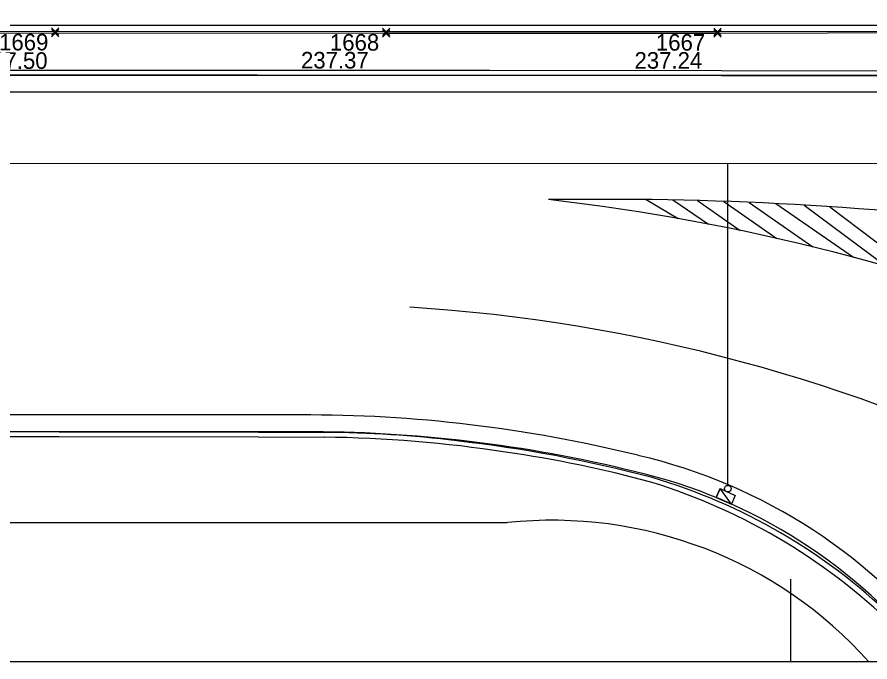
# Model space of a CAD drawing. Extents: x -264165 to -263733, y -1242319 to -1242245.
# Drawn here: x -263851.2 to -263825.46, y -1242319.19 to -1242299.73 of the extents above; entities that cross this region are included whole.
import ezdxf

# ---------------------------------------------------------------- set-up
doc = ezdxf.new("R2010")
doc.units = 0
for name, color, linetype in [('KFA_BOD_CISLO', 7, 'Continuous'), ('KFA_BOD_SYMBOL', 7, 'Continuous'), ('KFA_BOD_VYSKA', 7, 'Continuous'), ('KFA_SO_20-2_OBRUBNIKY_HORNA_HRANA', 7, 'Continuous'), ('PROJEKT_OBRUBNIKY_KOMUNIKACIE', 7, 'Continuous'), ('PROJEKT_TDZ_VODOROVNE', 7, 'Continuous'), ('RAM_NA_TLAC_1-250', 7, 'Continuous'), ('SITUACIA_DSP_2D', 7, 'Continuous'), ('SO_20-1_OBRUBNIKY_DOLNA_HRANA', 7, 'Continuous'), ('SO_20-1_OBRUBNIKY_HORNA_HRANA', 7, 'Continuous')]:
    doc.layers.add(name, color=color, linetype=linetype)

msp = doc.modelspace()

# ---------------------------------------------------------------- linework, layer by layer
at = {"layer": 'KFA_BOD_SYMBOL'}
for p, q in [((-263850.165, -1242300.271), (-263849.943, -1242300.049)), ((-263849.943, -1242300.271), (-263850.165, -1242300.049)), ((-263850.165, -1242300.32), (-263849.943, -1242300.1)), ((-263849.943, -1242300.32), (-263850.165, -1242300.1)), ((-263840.171, -1242300.282), (-263839.949, -1242300.061)), ((-263839.949, -1242300.282), (-263840.171, -1242300.061)), ((-263840.171, -1242300.332), (-263839.949, -1242300.11)), ((-263839.949, -1242300.332), (-263840.171, -1242300.11)), ((-263830.172, -1242300.282), (-263829.951, -1242300.061)), ((-263829.951, -1242300.282), (-263830.172, -1242300.061)), ((-263830.172, -1242300.332), (-263829.951, -1242300.11)), ((-263829.951, -1242300.332), (-263830.172, -1242300.11))]:
    msp.add_line(p, q, dxfattribs=at)
at = {"layer": 'KFA_SO_20-2_OBRUBNIKY_HORNA_HRANA'}
for points in [[(-263818.454, -1242300.127), (-263820.114, -1242300.153), (-263830.062, -1242300.171), (-263840.06, -1242300.171), (-263850.054, -1242300.16), (-263860.027, -1242300.174), (-263870.031, -1242300.18), (-263880.008, -1242300.187), (-263888.684, -1242300.195), (-263899.013, -1242300.19), (-263908.987, -1242300.212), (-263915.978, -1242300.22), (-263917.721, -1242300.207)], [(-263818.504, -1242300.177), (-263820.112, -1242300.193), (-263830.062, -1242300.221), (-263840.06, -1242300.221), (-263850.054, -1242300.21), (-263860.027, -1242300.224), (-263870.031, -1242300.23), (-263880.008, -1242300.237), (-263888.684, -1242300.245), (-263899.013, -1242300.24), (-263908.987, -1242300.262), (-263915.978, -1242300.27), (-263917.654, -1242300.257)]]:
    msp.add_lwpolyline(points, dxfattribs=at)
at = {"layer": 'PROJEKT_OBRUBNIKY_KOMUNIKACIE'}
for p, q in [((-263816.308, -1242299.982), (-263918.049, -1242299.982)), ((-263914.08, -1242301.482), (-263815.822, -1242301.482)), ((-263842.601, -1242312.24), (-263924.192, -1242312.232)), ((-264038.443, -1242314.982), (-263836.403, -1242314.982))]:
    msp.add_line(p, q, dxfattribs=at)
for centre, radius, start, end in [((-263842.427, -1242353.351), 41.111, 76.1362, 90.2415), ((-263836.184, -1242329.025), 16, 37.9535, 76.9695), ((-263835.045, -1242327.715), 12.805, 41.7702, 96.0874)]:
    msp.add_arc(centre, radius, start, end, dxfattribs=at)
at = {"layer": 'PROJEKT_TDZ_VODOROVNE'}
for p, q in [((-263913.857, -1242301.982), (-263816.374, -1242301.982)), ((-263832.039, -1242305.232), (-263835.165, -1242305.232)), ((-263832.216, -1242305.232), (-263831.251, -1242305.806)), ((-263831.408, -1242305.243), (-263830.341, -1242305.974)), ((-263830.671, -1242305.261), (-263829.376, -1242306.167)), ((-263829.878, -1242305.286), (-263828.277, -1242306.405)), ((-263829.11, -1242305.316), (-263827.186, -1242306.661)), ((-263828.303, -1242305.354), (-263825.963, -1242306.972)), ((-263827.448, -1242305.4), (-263824.977, -1242307.241)), ((-263826.672, -1242305.448), (-263823.87, -1242307.573)), ((-263842.661, -1242311.732), (-263980.94, -1242311.732))]:
    msp.add_line(p, q, dxfattribs=at)
for centre, radius, start, end in [((-263842.678, -1242370.168), 65.369, 68.01969, 83.40081), ((-263833.602, -1242410.935), 105.714, 80.83552, 89.15278), ((-263842.518, -1242358.966), 50.583, 63.4329, 86.4022), ((-263842.485, -1242353.555), 41.823, 76.1362, 90.2415), ((-263836.225, -1242329.073), 16.555, 36.9462, 76.8694)]:
    msp.add_arc(centre, radius, start, end, dxfattribs=at)
at = {"layer": 'RAM_NA_TLAC_1-250'}
msp.add_line((-263827.863, -1242316.685), (-263827.863, -1242319.185), dxfattribs=at)
msp.add_lwpolyline([(-264165.363, -1242244.935), (-263732.863, -1242244.935), (-263732.863, -1242319.185), (-264165.363, -1242319.185)], close=True, dxfattribs=at)
at = {"layer": 'SITUACIA_DSP_2D'}
for p, q in [((-263816.308, -1242299.982), (-263918.049, -1242299.982)), ((-263914.08, -1242301.482), (-263815.822, -1242301.482)), ((-263809.091, -1242304.153), (-263853.415, -1242304.148)), ((-263829.755, -1242313.856), (-263829.755, -1242304.151)), ((-263842.601, -1242312.24), (-263924.192, -1242312.232)), ((-263830.101, -1242314.219), (-263829.983, -1242313.954)), ((-263829.983, -1242313.954), (-263830.101, -1242314.219)), ((-263829.983, -1242313.954), (-263829.527, -1242314.158)), ((-263829.645, -1242314.423), (-263829.983, -1242313.954)), ((-263829.645, -1242314.423), (-263829.983, -1242313.954)), ((-263829.645, -1242314.423), (-263830.101, -1242314.219)), ((-263830.101, -1242314.219), (-263829.645, -1242314.423)), ((-263829.527, -1242314.158), (-263829.645, -1242314.423)), ((-264038.443, -1242314.982), (-263836.403, -1242314.982))]:
    msp.add_line(p, q, dxfattribs=at)
msp.add_circle((-263829.755, -1242313.956), 0.1, dxfattribs=at)
for centre, radius, start, end in [((-263842.427, -1242353.351), 41.111, 76.1362, 90.2415), ((-263836.184, -1242329.025), 16, 37.9534, 76.9695), ((-263835.045, -1242327.715), 12.805, 41.7701, 96.0874)]:
    msp.add_arc(centre, radius, start, end, dxfattribs=at)
at = {"layer": 'SO_20-1_OBRUBNIKY_DOLNA_HRANA'}
for points in [[(-263913.884, -1242301.489), (-263907.893, -1242301.489), (-263900.89, -1242301.488), (-263893.898, -1242301.483), (-263886.917, -1242301.473), (-263879.922, -1242301.465), (-263872.91, -1242301.469), (-263865.929, -1242301.465), (-263859.932, -1242301.473), (-263850.941, -1242301.471), (-263843.947, -1242301.471), (-263836.942, -1242301.481), (-263829.943, -1242301.484), (-263823.945, -1242301.487), (-263818.452, -1242301.495), (-263816.42, -1242301.504)], [(-263855.93, -1242312.232), (-263849.929, -1242312.239), (-263843.916, -1242312.251), (-263841.932, -1242312.261)]]:
    msp.add_lwpolyline(points, dxfattribs=at)
for centre, major_axis, ratio, start_param, end_param in [((-263842.029, -1242344.44), (-32.124, -3.857), 0.994471, 4.466507, 4.590549), ((-263842.443, -1242352.313), (-40.262, 2.734), 0.992518, 4.518911, 4.667632), ((-263836.917, -1242330.389), (-12.568, 12.147), 0.998664, 4.713467, 5.197044)]:
    msp.add_ellipse(centre, major_axis=major_axis, ratio=ratio, start_param=start_param, end_param=end_param, dxfattribs=at)
at = {"layer": 'SO_20-1_OBRUBNIKY_HORNA_HRANA'}
for points in [[(-263913.884, -1242301.344), (-263907.893, -1242301.343), (-263900.896, -1242301.344), (-263893.895, -1242301.338), (-263886.916, -1242301.328), (-263879.921, -1242301.324), (-263872.911, -1242301.324), (-263865.928, -1242301.325), (-263859.931, -1242301.327), (-263850.935, -1242301.324), (-263843.941, -1242301.331), (-263836.939, -1242301.332), (-263829.941, -1242301.342), (-263823.94, -1242301.343), (-263818.456, -1242301.352), (-263816.413, -1242301.358)], [(-263855.926, -1242312.378), (-263849.928, -1242312.38), (-263843.916, -1242312.392), (-263841.931, -1242312.403)]]:
    msp.add_lwpolyline(points, dxfattribs=at)
for centre, major_axis, ratio, start_param, end_param in [((-263842.277, -1242350.519), (-36.177, 12.321), 0.997094, 4.886995, 5.030708), ((-263841.309, -1242347.152), (-34.744, 1.786), 0.995607, 4.494833, 4.62376), ((-263837.329, -1242331.009), (-13.346, 12.171), 0.997839, 4.663107, 5.155176)]:
    msp.add_ellipse(centre, major_axis=major_axis, ratio=ratio, start_param=start_param, end_param=end_param, dxfattribs=at)

# ---------------------------------------------------------------- texts
at = {"layer": 'KFA_BOD_CISLO'}
for s, p in [('1669', (-263851.743, -1242300.732)), ('1668', (-263841.76, -1242300.738)), ('1667', (-263831.923, -1242300.738))]:
    msp.add_text(s, height=0.5, dxfattribs=at).set_placement(p)
at = {"layer": 'KFA_BOD_VYSKA'}
for s, p in [('237.50', (-263852.325, -1242301.289)), ('237.37', (-263842.633, -1242301.277)), ('237.24', (-263832.569, -1242301.283))]:
    msp.add_text(s, height=0.5, dxfattribs=at).set_placement(p)

doc.saveas('drawing.dxf')
